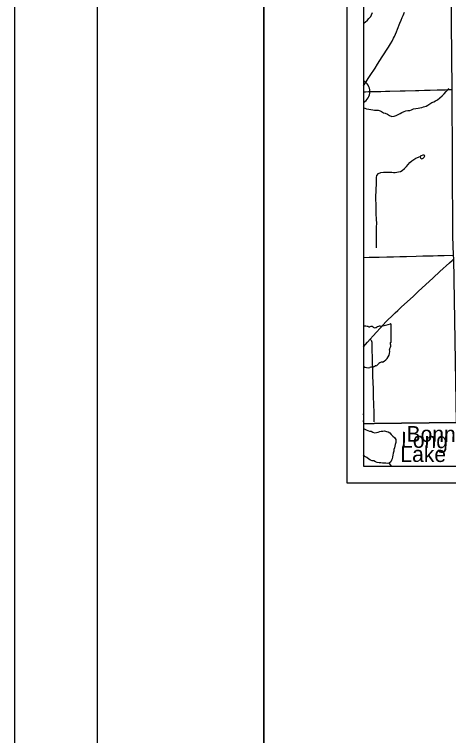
# Model space of a CAD drawing. Extents: x 0 to 34, y 0 to 22.
# Drawn here: x 0 to 2.612, y 12.477 to 16.821 of the extents above; entities that cross this region are included whole.
import ezdxf

# ---------------------------------------------------------------- set-up
doc = ezdxf.new("R2010")
doc.units = 0
for name, color, linetype in [('Default', 7, 'Continuous'), ('GM_X_County_Road', 7, 'Continuous'), ('GM_X_Minor_Lake', 7, 'Continuous'), ('GM_X_Minor_Lake_Text', 7, 'Continuous'), ('GM_X_Minor_River', 7, 'Continuous'), ('GM_X_Minor_River_Text', 7, 'Continuous'), ('GM_X_State_Location', 7, 'Continuous'), ('GM_X_State_Route', 7, 'Continuous'), ('GM_X_Township_Road', 7, 'Continuous'), ('SH_Border', 7, 'Continuous'), ('SH_Cut_Line', 7, 'Continuous'), ('SH_Data', 7, 'Continuous')]:
    doc.layers.add(name, color=color, linetype=linetype)

msp = doc.modelspace()

# ---------------------------------------------------------------- linework, layer by layer
at = {"layer": 'Default'}
for p, q in [((2.1, 16.421), (2.1, 16.2911)), ((2.1, 14.9419), (2.1, 14.7021))]:
    msp.add_line(p, q, dxfattribs=at)
for points in [[(2.1, 18.375), (2.1, 14.3539), (2.1651, 14.3567), (2.6607, 14.3625), (2.6434, 15.3487), (2.6428, 15.3713), (2.6388, 15.4856), (2.6332, 16.3685), (2.6231, 17.3771), (2.6129, 17.8818), (2.6122, 18.05), (2.6118, 18.3803)], [(2.1, 14.3539), (2.1, 14.1), (3.6803, 14.1), (3.6708, 14.3479), (3.5171, 14.3547), (3.1736, 14.3499), (2.7339, 14.3605), (2.6607, 14.3625), (2.1651, 14.3567)]]:
    msp.add_lwpolyline(points, close=True, dxfattribs=at)
msp.add_lwpolyline([(2.2665, 14.8486), (2.2665, 14.8486), (2.2665, 14.8485), (2.2665, 14.9534)], dxfattribs=at)
for centre, radius, start, end in [((2.0638, 16.3561), 0.0744, 299.1303, 60.8697), ((2.1726, 15.2211), 0.2796, 275.8445, 288.9065), ((2.2636, 14.9537), 0.00294, 355.0978, 97.738), ((2.1011, 14.9715), 0.0296, 267.9154, 271.1117), ((2.1109, 14.8359), 0.1064, 80.4867, 94.9883), ((2.135, 14.9463), 0.00855, 219.7921, 297.1024), ((2.1476, 14.9232), 0.0178, 54.4667, 119.1411), ((2.1705, 14.9549), 0.0214, 233.8562, 294.8282), ((2.2083, 14.8871), 0.0563, 97.3462, 120.7689), ((2.2771, 14.8047), 0.0198, 136.8065, 186.9296), ((2.2659, 14.8409), 0.00454, 107.944, 210.337), ((2.237, 14.8276), 0.0273, 340.033, 23.6496), ((2.2634, 14.8481), 0.00314, 289.6038, 7.7341), ((2.1883, 14.7914), 0.0699, 292.3089, 8.9858), ((2.2178, 14.6885), 0.0383, 94.4031, 142.5768), ((2.0581, 14.6548), 0.0632, 47.1842, 48.4105), ((2.1264, 14.7322), 0.0401, 230.7004, 286.2918), ((2.1496, 14.663), 0.0329, 85.6951, 111.21), ((2.1525, 14.7172), 0.0214, 268.777, 315.5493), ((2.1718, 14.6978), 0.00601, 65.7517, 132.6484), ((2.1692, 14.7253), 0.0226, 282.8732, 323.2771)]:
    msp.add_arc(centre, radius, start, end, dxfattribs=at)
at = {"layer": 'GM_X_County_Road'}
for points in [[(2.1, 16.3898), (2.1042, 16.3962), (2.1159, 16.4143), (2.1293, 16.4352), (2.141, 16.4536), (2.1696, 16.4979), (2.1848, 16.5213), (2.2135, 16.5653), (2.2253, 16.5835), (2.2387, 16.6044), (2.2501, 16.6229), (2.263, 16.6442), (2.2724, 16.6603), (2.2814, 16.6767), (2.2868, 16.6879), (2.293, 16.7022), (2.299, 16.7166), (2.3048, 16.731), (2.3196, 16.7684), (2.3267, 16.7856), (2.3339, 16.8028), (2.3387, 16.8142), (2.347, 16.8343)], [(2.1, 16.3548), (2.1125, 16.3552), (2.1312, 16.3556), (2.1529, 16.3559), (2.2056, 16.3573), (2.2336, 16.3582), (2.2584, 16.3588), (2.3206, 16.3601), (2.3517, 16.3612), (2.4138, 16.3625), (2.4324, 16.363), (2.4665, 16.364), (2.4789, 16.3645), (2.4882, 16.3648), (2.5006, 16.3652), (2.5439, 16.3662), (2.5719, 16.3668), (2.5936, 16.3671), (2.6122, 16.3676), (2.6335, 16.3679)]]:
    msp.add_lwpolyline(points, dxfattribs=at)
at = {"layer": 'GM_X_Minor_Lake'}
for points in [[(2.4441, 15.9674), (2.4422, 15.9662), (2.4415, 15.9653), (2.441, 15.9638), (2.443, 15.9557)], [(2.443, 15.9557), (2.4517, 15.9511), (2.4593, 15.9546), (2.4661, 15.9603), (2.4687, 15.9679), (2.4649, 15.9728), (2.4581, 15.9736), (2.4482, 15.9697), (2.4441, 15.9674)], [(2.1, 14.324), (2.1043, 14.3235), (2.116, 14.3185), (2.1258, 14.3146), (2.1356, 14.3111), (2.1455, 14.3095), (2.1557, 14.3037), (2.1674, 14.3006), (2.1776, 14.302), (2.1883, 14.3053), (2.1978, 14.3079), (2.2073, 14.3097), (2.2175, 14.3111), (2.2274, 14.3118), (2.2383, 14.3086), (2.2482, 14.3055), (2.258, 14.3001), (2.267, 14.2894), (2.2771, 14.2802), (2.2869, 14.2714), (2.2952, 14.2607), (2.2943, 14.2509), (2.2939, 14.2414), (2.2915, 14.2308), (2.2888, 14.2202), (2.2876, 14.2103), (2.2837, 14.1998), (2.2825, 14.1892), (2.2793, 14.1774), (2.277, 14.1661), (2.275, 14.1555), (2.273, 14.1445), (2.2695, 14.1347), (2.2652, 14.1248), (2.2549, 14.1177), (2.2454, 14.1148), (2.2349, 14.1168), (2.2242, 14.1176), (2.2148, 14.1173), (2.2042, 14.1189), (2.1936, 14.1194), (2.183, 14.1222), (2.1732, 14.1264), (2.1626, 14.1311), (2.1527, 14.1312), (2.1429, 14.1347), (2.1316, 14.1412), (2.1195, 14.1508), (2.109, 14.1581), (2.1, 14.1673)]]:
    msp.add_lwpolyline(points, dxfattribs=at)
at = {"layer": 'GM_X_Minor_River'}
for points in [[(2.1, 16.7648), (2.1103, 16.7741), (2.125, 16.7863), (2.1333, 16.7959), (2.1435, 16.8084), (2.1484, 16.8191), (2.1536, 16.8331)], [(2.2316, 16.2262), (2.2456, 16.2202), (2.2566, 16.2115), (2.2703, 16.2066), (2.2851, 16.2078), (2.2976, 16.2117), (2.3089, 16.217), (2.3202, 16.2243), (2.3308, 16.23), (2.3448, 16.2361), (2.355, 16.2403), (2.3672, 16.2427), (2.3785, 16.2427), (2.3884, 16.2462), (2.4012, 16.2519), (2.4149, 16.2542), (2.4285, 16.2569), (2.4402, 16.2585), (2.452, 16.2608), (2.4618, 16.2635), (2.4766, 16.2689), (2.4868, 16.2738), (2.4993, 16.2819), (2.511, 16.2906), (2.5227, 16.2949), (2.5344, 16.2998), (2.5462, 16.3067), (2.559, 16.3178), (2.5733, 16.33), (2.5862, 16.3425), (2.5979, 16.3559), (2.613, 16.3749)], [(2.1, 16.2583), (2.109, 16.255), (2.1189, 16.2523), (2.1318, 16.2497), (2.1454, 16.2475), (2.1572, 16.2453), (2.1671, 16.2446), (2.1777, 16.2446), (2.1887, 16.2439), (2.1997, 16.2405), (2.2095, 16.236), (2.2209, 16.2288), (2.2316, 16.2262)], [(2.1792, 15.4154), (2.1784, 15.4253), (2.1776, 15.4359), (2.1779, 15.4488), (2.1782, 15.4602), (2.1782, 15.4697), (2.178, 15.5247), (2.1787, 15.5342), (2.1794, 15.5456), (2.1797, 15.557), (2.1797, 15.568), (2.1785, 15.5809), (2.1777, 15.5957), (2.1772, 15.6105), (2.1768, 15.6218), (2.1771, 15.634), (2.177, 15.6602), (2.1758, 15.6731), (2.1758, 15.686), (2.1754, 15.697), (2.1752, 15.7338), (2.1763, 15.7482), (2.1766, 15.7585), (2.1773, 15.7679), (2.1773, 15.7782), (2.178, 15.7888), (2.1791, 15.8029), (2.1787, 15.8169), (2.1782, 15.8287), (2.179, 15.8385), (2.18, 15.8511), (2.1906, 15.8629), (2.2054, 15.8679), (2.2209, 15.8706), (2.2364, 15.871), (2.2486, 15.8707), (2.2584, 15.8703), (2.2702, 15.87), (2.2808, 15.8693), (2.2906, 15.8693), (2.3009, 15.8701), (2.3118, 15.8721), (2.3224, 15.8751), (2.3326, 15.8805), (2.3474, 15.8923), (2.3591, 15.9045), (2.3689, 15.9167), (2.3798, 15.9292), (2.3908, 15.9395), (2.4025, 15.9468), (2.4157, 15.954), (2.4256, 15.959), (2.4411, 15.9643)], [(2.1, 14.3661), (2.1005, 14.3688), (2.1024, 14.3818), (2.1027, 14.392), (2.1023, 14.4026), (2.1007, 14.4125), (2.1, 14.4153)], [(2.2687, 14.1), (2.2639, 14.1059), (2.2568, 14.1154), (2.2549, 14.1177)]]:
    msp.add_lwpolyline(points, dxfattribs=at)
at = {"layer": 'GM_X_State_Route'}
msp.add_lwpolyline([(2.1, 14.819), (2.1251, 14.8471), (2.1408, 14.8645), (2.1583, 14.8839), (2.179, 14.907), (2.1997, 14.9302), (2.2353, 14.9691), (2.2482, 14.9825), (2.2682, 15.002), (2.291, 15.023), (2.3069, 15.0378), (2.3275, 15.0567), (2.4005, 15.124), (2.4301, 15.1514), (2.5189, 15.2336), (2.5599, 15.2716), (2.617, 15.3242), (2.6331, 15.3388), (2.6436, 15.3481)], dxfattribs=at)
at = {"layer": 'GM_X_Township_Road'}
for points in [[(2.1, 15.3565), (2.1347, 15.3575), (2.1565, 15.3582), (2.1938, 15.359), (2.2405, 15.3602), (2.2809, 15.3614), (2.3182, 15.3623), (2.3586, 15.3633), (2.4177, 15.3648), (2.4581, 15.3659), (2.4891, 15.3664), (2.5202, 15.3673), (2.5482, 15.3682), (2.5855, 15.3689), (2.643, 15.3707)], [(2.1636, 14.436), (2.163, 14.457), (2.162, 14.4817), (2.1609, 14.5095), (2.1605, 14.5281), (2.1598, 14.5591), (2.1583, 14.6087), (2.1573, 14.6366), (2.1565, 14.6582), (2.1559, 14.6737), (2.1555, 14.6891), (2.1546, 14.7199), (2.1539, 14.7443), (2.1536, 14.7687), (2.1534, 14.7842), (2.1527, 14.8121), (2.1522, 14.84), (2.1521, 14.8431), (2.1517, 14.8462), (2.1511, 14.8492), (2.15, 14.852), (2.1485, 14.8547), (2.1467, 14.8573), (2.1447, 14.8596), (2.1408, 14.8645)], [(2.1654, 14.3672), (2.1647, 14.394), (2.1639, 14.426), (2.1636, 14.436)]]:
    msp.add_lwpolyline(points, dxfattribs=at)
at = {"layer": 'SH_Border'}
for points in [[(0.5, 21.5), (1.5, 21.5), (1.5, 0.5), (0.5, 0.5)], [(1.5, 21.5), (33.5, 21.5), (33.5, 0.5), (1.5, 0.5)]]:
    msp.add_lwpolyline(points, close=True, dxfattribs=at)
at = {"layer": 'SH_Cut_Line'}
for points in [[(0, 0), (34, 0), (34, 22), (0, 22)], [(2.6032, 20.9), (2.1, 20.9), (2.1, 14.3539), (2.1651, 14.3567), (2.6607, 14.3625), (2.6434, 15.3487), (2.6428, 15.3713), (2.6388, 15.4856), (2.6332, 16.3685), (2.6231, 17.3771), (2.6129, 17.8818), (2.6122, 18.05), (2.6118, 18.3803), (2.6161, 18.3799), (2.6204, 18.3797), (2.6263, 18.3795), (2.6292, 18.3794), (2.6281, 18.8843), (2.6224, 19.9515), (2.6032, 20.8721)]]:
    msp.add_lwpolyline(points, close=True, dxfattribs=at)
msp.add_lwpolyline([(2.6607, 14.3625), (2.1651, 14.3567), (2.1, 14.3539), (2.1, 14.1), (8.9, 14.1)], dxfattribs=at)
at = {"layer": 'SH_Data'}
for p, q in [((2, 21), (2, 14)), ((2.1, 20.9), (2.1, 14.1)), ((2.1, 14.1), (8.9, 14.1)), ((2.1, 14.1), (2.1, 14.1)), ((2, 14), (9, 14))]:
    msp.add_line(p, q, dxfattribs=at)

# ---------------------------------------------------------------- texts
at = {"layer": 'GM_X_Minor_Lake_Text'}
for s, rotation, p in [('Bonnett', 359.8803, (2.3594, 14.2465)), ('Lake', 359.8805, (2.3223, 14.1251))]:
    msp.add_text(s, height=0.09471, rotation=rotation, dxfattribs=at).set_placement(p)
at = {"layer": 'GM_X_Minor_River_Text'}
msp.add_text('Long', height=0.09471, rotation=358.9929, dxfattribs=at).set_placement((2.3263, 14.2119))
at = {"layer": 'GM_X_State_Location'}
msp.add_text('3', height=0.000189, rotation=0, dxfattribs=at).set_placement((2.1032, 14.8177))
for s in ['s', 'r']:
    msp.add_text(s, height=0.000189, dxfattribs=at).set_placement((2.1317, 14.8315))

doc.saveas('drawing.dxf')
